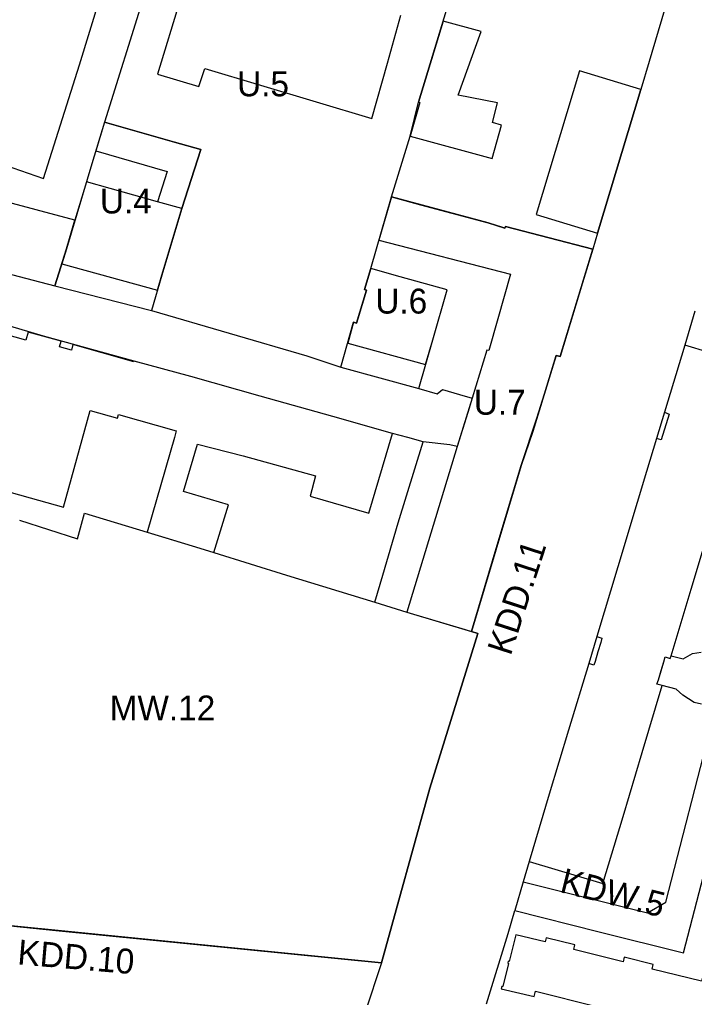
# Model space of a CAD drawing. Extents: x 7424052 to 7425705, y 5546602 to 5547569.
# Drawn here: x 7425164.6 to 7425299.9, y 5547085.1 to 5547281.2 of the extents above; entities that cross this region are included whole.
import ezdxf

# ---------------------------------------------------------------- set-up
doc = ezdxf.new("R2010")
doc.units = 0
for name, color, linetype in [('linia regulacyjna wysokości zabudowy', 7, 'Continuous'), ('linie rozgraniczające', 7, 'Continuous'), ('nieprzekraczalne linie zabudowy', 7, 'Continuous'), ('obowiazujace linie zabudowy', 7, 'Continuous'), ('przeznaczenia terenów', 7, 'Continuous')]:
    doc.layers.add(name, color=color, linetype=linetype)

msp = doc.modelspace()

# ---------------------------------------------------------------- linework, layer by layer
at = {"layer": 'linia regulacyjna wysokości zabudowy'}
msp.add_lwpolyline([(7425197.12, 5547243.31), (7425192.26, 5547244.61), (7425177.99, 5547248.62)], dxfattribs=at)
at = {"layer": 'linie rozgraniczające'}
for p, q in [((7425193.55, 5547299.05), (7425181.63, 5547260.6)), ((7425244.57, 5547264.62), (7425250.17, 5547283.05)), ((7425293.89, 5547283.1), (7425290.81, 5547272.76)), ((7425290.81, 5547272.76), (7425289.13, 5547267.14)), ((7425289.13, 5547267.14), (7425280.45, 5547238.31)), ((7425242.87, 5547257.77), (7425244.57, 5547264.62)), ((7425181.63, 5547260.6), (7425179.09, 5547252.28)), ((7425181.63, 5547260.6), (7425195.65, 5547256.62)), ((7425239.14, 5547245.61), (7425242.87, 5547257.77)), ((7425195.65, 5547256.62), (7425200.92, 5547255.12)), ((7425200.92, 5547255.12), (7425197.12, 5547243.31)), ((7425179.09, 5547252.28), (7425173.96, 5547235.21)), ((7425234.98, 5547231.25), (7425239.14, 5547245.61)), ((7425239.14, 5547245.61), (7425244.98, 5547244.05)), ((7425244.98, 5547244.05), (7425258.56, 5547240.43)), ((7425197.12, 5547243.31), (7425193.09, 5547229.93)), ((7425258.56, 5547240.43), (7425260.2, 5547239.89)), ((7425260.2, 5547239.89), (7425261.9, 5547239.33)), ((7425261.9, 5547239.33), (7425262, 5547239.66)), ((7425262, 5547239.66), (7425279.53, 5547235.12)), ((7425280.45, 5547238.31), (7425279.53, 5547235.12)), ((7425173.96, 5547235.21), (7425171.67, 5547227.81)), ((7425279.53, 5547235.12), (7425277.46, 5547228.4)), ((7425151.52, 5547233.04), (7425171.67, 5547227.81)), ((7425233.76, 5547227.03), (7425234.98, 5547231.25)), ((7425240.91, 5547229.59), (7425234.98, 5547231.25)), ((7425193.09, 5547229.93), (7425191.05, 5547222.84)), ((7425250.29, 5547226.97), (7425240.91, 5547229.59)), ((7425277.46, 5547228.4), (7425272.98, 5547213.6)), ((7425171.67, 5547227.81), (7425191.05, 5547222.84)), ((7425232.13, 5547220.31), (7425234.15, 5547226.91)), ((7425234.15, 5547226.91), (7425233.76, 5547227.03)), ((7425247.43, 5547216.97), (7425250.29, 5547226.97)), ((7425191.05, 5547222.84), (7425222.18, 5547213.75)), ((7425299.97, 5547222.7), (7425297.97, 5547215.91)), ((7425169.36, 5547217.69), (7425159.3, 5547220.65)), ((7425229.01, 5547211.47), (7425231.54, 5547220.48)), ((7425231.54, 5547220.48), (7425232.13, 5547220.31)), ((7425187.54, 5547212.67), (7425169.36, 5547217.69)), ((7425244.63, 5547207.16), (7425247.43, 5547216.97)), ((7425297.97, 5547215.91), (7425293.87, 5547202.43)), ((7425198.94, 5547209.58), (7425187.54, 5547212.67)), ((7425222.18, 5547213.75), (7425229.01, 5547211.47)), ((7425272.15, 5547213.81), (7425271.29, 5547211.02)), ((7425272.98, 5547213.6), (7425272.15, 5547213.81)), ((7425229.01, 5547211.47), (7425244.63, 5547207.16)), ((7425271.29, 5547211.02), (7425267.5, 5547198.59)), ((7425212.84, 5547205.65), (7425198.94, 5547209.58)), ((7425244.63, 5547207.16), (7425248.29, 5547206.15)), ((7425248.29, 5547206.15), (7425249.36, 5547206.96)), ((7425249.36, 5547206.96), (7425252.8, 5547206.01)), ((7425227.4, 5547201.58), (7425212.84, 5547205.65)), ((7425252.8, 5547206.01), (7425255.31, 5547205.24)), ((7425255.31, 5547205.24), (7425254.44, 5547202.41)), ((7425239.36, 5547198.19), (7425227.4, 5547201.58)), ((7425254.44, 5547202.41), (7425252.34, 5547195.55)), ((7425293.87, 5547202.43), (7425292.3, 5547197.17)), ((7425267.5, 5547198.59), (7425265.15, 5547191.76)), ((7425242.4, 5547197.37), (7425239.36, 5547198.19)), ((7425245.51, 5547196.5), (7425242.4, 5547197.37)), ((7425292.3, 5547197.17), (7425290.3, 5547190.57)), ((7425240.52, 5547180.27), (7425245.51, 5547196.5)), ((7425250.88, 5547195.9), (7425245.51, 5547196.5)), ((7425252.34, 5547195.55), (7425250.88, 5547195.9)), ((7425265.15, 5547191.76), (7425255.17, 5547158.49)), ((7425290.3, 5547190.57), (7425288.42, 5547184.33)), ((7425288.42, 5547184.33), (7425284.53, 5547171.41)), ((7425176.17, 5547177.02), (7425177.57, 5547182.18)), ((7425177.57, 5547182.18), (7425190.17, 5547178.38)), ((7425164.56, 5547180.78), (7425176.17, 5547177.02)), ((7425237.41, 5547169.73), (7425240.52, 5547180.27)), ((7425190.17, 5547178.38), (7425200.75, 5547175.15)), ((7425200.75, 5547175.15), (7425203.55, 5547174.3)), ((7425203.55, 5547174.3), (7425218.12, 5547169.76)), ((7425284.53, 5547171.41), (7425280.32, 5547157.45)), ((7425218.12, 5547169.76), (7425235.81, 5547164.31)), ((7425235.81, 5547164.31), (7425237.41, 5547169.73)), ((7425235.81, 5547164.31), (7425242.22, 5547162.33)), ((7425242.22, 5547162.33), (7425242.87, 5547162.13)), ((7425242.87, 5547162.13), (7425253.93, 5547158.86)), ((7425256.44, 5547158.09), (7425246.86, 5547127.01)), ((7425253.93, 5547158.86), (7425255.17, 5547158.49)), ((7425255.17, 5547158.49), (7425256.44, 5547158.09)), ((7425280.32, 5547157.45), (7425278.7, 5547152.04)), ((7425295.03, 5547153.06), (7425295.24, 5547153.61)), ((7425295.24, 5547153.61), (7425297.65, 5547152.96)), ((7425297.65, 5547152.96), (7425299.48, 5547154.02)), ((7425299.48, 5547154.02), (7425301.26, 5547154.33)), ((7425278.7, 5547152.04), (7425274.67, 5547138.66)), ((7425292.66, 5547148.76), (7425293.77, 5547152.4)), ((7425293.77, 5547152.4), (7425294.06, 5547153.36)), ((7425294.06, 5547153.36), (7425295.03, 5547153.06)), ((7425292.39, 5547147.93), (7425292.66, 5547148.76)), ((7425293.45, 5547147.62), (7425292.39, 5547147.93)), ((7425296.26, 5547146.87), (7425293.45, 5547147.62)), ((7425297.55, 5547145.68), (7425296.26, 5547146.87)), ((7425299.83, 5547144.23), (7425297.55, 5547145.68)), ((7425301.29, 5547143.88), (7425299.83, 5547144.23)), ((7425294.16, 5547104.2), (7425303.47, 5547140.29)), ((7425274.67, 5547138.66), (7425270.8, 5547125.83)), ((7425297.73, 5547094.02), (7425309.28, 5547138.82)), ((7425246.86, 5547127.01), (7425237.13, 5547092.01)), ((7425270.8, 5547125.83), (7425266.73, 5547112.31)), ((7425266.73, 5547112.31), (7425265.56, 5547108.26)), ((7425265.56, 5547108.26), (7425263.9, 5547102.49)), ((7425265.56, 5547108.26), (7425290.5, 5547102.02)), ((7425262.57, 5547097.9), (7425263.9, 5547102.49)), ((7425263.9, 5547102.49), (7425280.82, 5547098.26)), ((7425290.5, 5547102.02), (7425294.16, 5547104.2)), ((7425171.61, 5547098.54), (7425146.14, 5547101.08)), ((7425237.13, 5547092.01), (7425171.61, 5547098.54)), ((7425258.21, 5547083.79), (7425262.57, 5547097.9)), ((7425280.82, 5547098.26), (7425297.73, 5547094.02)), ((7425237.13, 5547092.01), (7425233.89, 5547082.13))]:
    msp.add_line(p, q, dxfattribs=at)
at = {"layer": 'nieprzekraczalne linie zabudowy'}
for p, q in [((7425176.58, 5547272.07), (7425185.39, 5547301.08)), ((7425238.32, 5547272.41), (7425241.02, 5547282.04)), ((7425249.51, 5547280.87), (7425244.57, 5547264.62)), ((7425257.13, 5547278.79), (7425249.51, 5547280.87)), ((7425252.52, 5547266.03), (7425257.13, 5547278.79)), ((7425169.35, 5547249.33), (7425176.58, 5547272.07)), ((7425260.43, 5547264.45), (7425252.52, 5547266.03)), ((7425244.82, 5547264.55), (7425242.87, 5547257.77)), ((7425244.57, 5547264.62), (7425244.82, 5547264.55)), ((7425259.38, 5547260.51), (7425260.43, 5547264.45)), ((7425181.63, 5547260.6), (7425179.88, 5547254.83)), ((7425195.65, 5547256.62), (7425181.63, 5547260.6)), ((7425259.33, 5547253.31), (7425261.2, 5547260.01)), ((7425261.2, 5547260.01), (7425259.38, 5547260.51)), ((7425242.87, 5547257.77), (7425259.33, 5547253.31)), ((7425200.92, 5547255.12), (7425195.65, 5547256.62)), ((7425179.88, 5547254.83), (7425194.16, 5547250.69)), ((7425197.12, 5547243.31), (7425200.92, 5547255.12)), ((7425157.49, 5547253.4), (7425169.35, 5547249.33)), ((7425194.16, 5547250.69), (7425192.26, 5547244.61)), ((7425177.99, 5547248.62), (7425175.68, 5547240.94)), ((7425192.26, 5547244.61), (7425177.99, 5547248.62)), ((7425239.14, 5547245.61), (7425236.64, 5547236.96)), ((7425248.85, 5547243.02), (7425239.14, 5547245.61)), ((7425193.09, 5547229.93), (7425197.12, 5547243.31)), ((7425258.56, 5547240.43), (7425248.85, 5547243.02)), ((7425175.68, 5547240.94), (7425173.96, 5547235.21)), ((7425260.2, 5547239.89), (7425258.56, 5547240.43)), ((7425261.05, 5547239.61), (7425260.2, 5547239.89)), ((7425261.9, 5547239.33), (7425261.05, 5547239.61)), ((7425262, 5547239.66), (7425261.9, 5547239.33)), ((7425279.53, 5547235.12), (7425262, 5547239.66)), ((7425236.64, 5547236.96), (7425263.01, 5547230.11)), ((7425173.96, 5547235.21), (7425173.02, 5547232.18)), ((7425173.02, 5547232.18), (7425192.21, 5547226.88)), ((7425234.98, 5547231.25), (7425233.76, 5547227.03)), ((7425240.91, 5547229.59), (7425234.98, 5547231.25)), ((7425263.01, 5547230.11), (7425260.49, 5547221.18)), ((7425192.21, 5547226.88), (7425193.09, 5547229.93)), ((7425250.29, 5547226.97), (7425240.91, 5547229.59)), ((7425234.15, 5547226.91), (7425232.38, 5547221.13)), ((7425233.76, 5547227.03), (7425234.15, 5547226.91)), ((7425247.43, 5547216.97), (7425250.29, 5547226.97)), ((7425231.54, 5547220.48), (7425230.37, 5547216.3)), ((7425232.13, 5547220.31), (7425231.54, 5547220.48)), ((7425232.38, 5547221.13), (7425232.13, 5547220.31)), ((7425260.49, 5547221.18), (7425258.69, 5547214.79)), ((7425230.37, 5547216.3), (7425245.96, 5547211.98)), ((7425245.96, 5547211.98), (7425247.43, 5547216.97)), ((7425258.29, 5547214.91), (7425255.31, 5547205.24)), ((7425258.69, 5547214.79), (7425258.29, 5547214.91)), ((7425255.31, 5547205.24), (7425252.34, 5547195.55)), ((7425252.34, 5547195.55), (7425242.22, 5547162.33)), ((7425242.22, 5547162.33), (7425255.17, 5547158.49)), ((7425246.86, 5547127.01), (7425256.44, 5547158.09)), ((7425256.44, 5547158.09), (7425255.17, 5547158.49)), ((7425237.13, 5547092.01), (7425246.86, 5547127.01)), ((7425144.77, 5547101.25), (7425171.85, 5547098.52)), ((7425171.85, 5547098.52), (7425237.13, 5547092.01))]:
    msp.add_line(p, q, dxfattribs=at)
at = {"layer": 'obowiazujace linie zabudowy'}
for p, q in [((7425175.68, 5547240.94), (7425155.33, 5547246.36)), ((7425173.96, 5547235.21), (7425175.68, 5547240.94)), ((7425171.67, 5547227.81), (7425173.96, 5547235.21)), ((7425151.52, 5547233.04), (7425171.67, 5547227.81))]:
    msp.add_line(p, q, dxfattribs=at)
for points in [[(7425196.81, 5547285.4), (7425192.23, 5547270.21), (7425200.55, 5547267.75), (7425201.69, 5547271.37), (7425235.23, 5547261.37), (7425238.32, 5547272.41)], [(7425289.13, 5547267.14), (7425276.82, 5547270.87), (7425268.17, 5547242.08), (7425280.45, 5547238.31), (7425289.13, 5547267.14)], [(7425255.17, 5547158.49), (7425260.16, 5547175.12), (7425265.15, 5547191.76), (7425268.32, 5547201.27), (7425269.8, 5547206.15), (7425272.15, 5547213.81), (7425272.98, 5547213.6), (7425279.53, 5547235.12)], [(7425157.81, 5547187.71), (7425173.37, 5547183.41), (7425178.72, 5547202.79), (7425184.23, 5547201.26), (7425184.43, 5547201.95), (7425196, 5547198.7), (7425195.63, 5547197.35), (7425192.04, 5547184.86), (7425190.17, 5547178.38), (7425193.73, 5547177.29), (7425200.75, 5547175.15), (7425203.55, 5547174.3), (7425206.44, 5547183.89), (7425197.44, 5547186.56), (7425200.25, 5547196.06), (7425209.4, 5547193.71), (7425223.89, 5547189.66), (7425222.81, 5547185.57), (7425234.59, 5547182.18), (7425239.36, 5547198.19), (7425227.4, 5547201.58), (7425212.84, 5547205.65), (7425198.94, 5547209.58), (7425187.54, 5547212.67), (7425187.5, 5547212.53), (7425175.27, 5547216.04), (7425174.95, 5547214.9), (7425172.59, 5547215.55), (7425172.91, 5547216.69), (7425166.31, 5547218.52), (7425165.85, 5547216.87), (7425159.35, 5547218.66)], [(7425312.62, 5547211.48), (7425297.97, 5547215.91), (7425293.87, 5547202.43), (7425294.86, 5547202.03), (7425293.26, 5547196.88), (7425293.26, 5547196.88), (7425292.3, 5547197.17), (7425290.3, 5547190.57), (7425288.42, 5547184.33), (7425284.53, 5547171.41), (7425280.32, 5547157.45), (7425281.34, 5547157.09), (7425281.11, 5547156.28), (7425280.56, 5547154.38), (7425280, 5547152.47), (7425279.75, 5547151.72), (7425278.7, 5547152.04), (7425274.67, 5547138.66), (7425270.8, 5547125.83), (7425266.73, 5547112.31), (7425281.53, 5547107.91), (7425285.58, 5547121.38), (7425289.43, 5547134.2), (7425293.45, 5547147.62), (7425292.39, 5547147.93), (7425292.66, 5547148.76), (7425293.22, 5547150.64), (7425293.77, 5547152.4), (7425294.06, 5547153.36), (7425295.03, 5547153.06), (7425295.24, 5547153.61), (7425299.23, 5547166.94), (7425303.12, 5547179.86)], [(7425309.25, 5547086.36), (7425307.2, 5547086.84), (7425307.37, 5547087.76), (7425301.55, 5547089.21), (7425301.31, 5547088.34), (7425291.44, 5547090.76), (7425291.59, 5547091.7), (7425285.84, 5547093.13), (7425285.59, 5547092.24), (7425275.72, 5547094.71), (7425275.92, 5547095.64), (7425270.15, 5547097.05), (7425269.97, 5547096.24), (7425264.11, 5547097.66), (7425262.75, 5547092.29), (7425262.55, 5547092.33), (7425262.45, 5547091.94), (7425262.63, 5547091.89), (7425261.47, 5547087.26), (7425261.25, 5547087.29), (7425261.14, 5547086.81), (7425267.78, 5547085.24), (7425268.05, 5547086.33), (7425304.7, 5547077.14)]]:
    msp.add_lwpolyline(points, dxfattribs=at)

# ---------------------------------------------------------------- texts
at = {"layer": 'przeznaczenia terenów'}
for s, p in [('U.5', (7425208.19, 5547265.79)), ('U.4', (7425180.68, 5547242.29)), ('U.6', (7425235.91, 5547222.22)), ('U.7', (7425255.66, 5547201.93)), ('MW.12', (7425182.64, 5547140.62))]:
    msp.add_text(s, height=5, dxfattribs=at).set_placement(p)
for s, rotation, p in [('KDD.11', 72, (7425263.03, 5547153.43)), ('KDW.5', 346, (7425272.69, 5547106.23)), ('KDD.10', 355.1048, (7425164.03, 5547091.72))]:
    msp.add_text(s, height=5, rotation=rotation, dxfattribs=at).set_placement(p)

doc.saveas('drawing.dxf')
